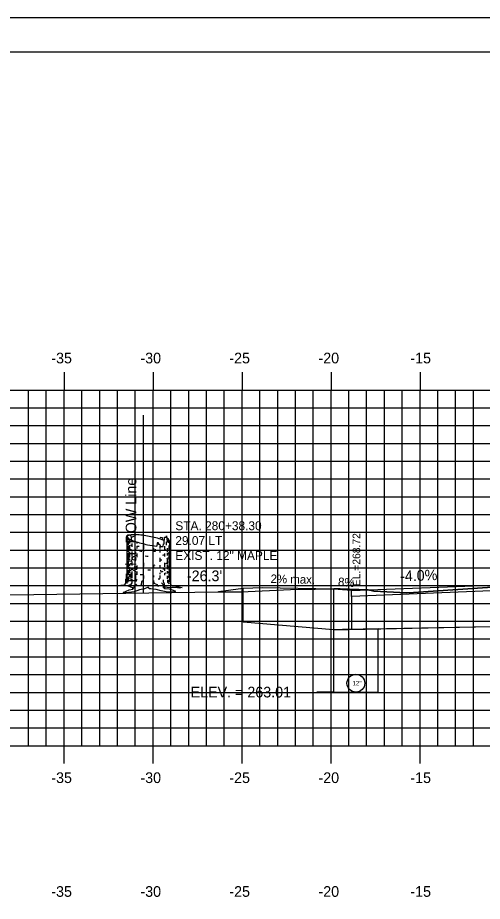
# Model space of a CAD drawing. Extents: x 855121 to 855291, y 366268 to 366378.
# Drawn here: x 855166.83 to 855192.94, y 366328.48 to 366378.18 of the extents above; entities that cross this region are included whole.
import ezdxf

# ---------------------------------------------------------------- set-up
doc = ezdxf.new("R2010")
doc.units = 0
for name, color, linetype in [('ANNOTATION', 7, 'Continuous'), ('BORDER', 7, 'Continuous'), ('D_Roadway_Drive_Gravel_LT', 7, 'Continuous'), ('D_Roadway_Drive_SubGrade', 7, 'Continuous'), ('D_Roadway_Edge_Shoulder', 7, 'Continuous'), ('D_Roadway_SubGrade', 7, 'Continuous'), ('D_Text_Monospaced', 7, 'Continuous'), ('D_Text_Standard', 7, 'Continuous'), ('E_ROW_Line', 7, 'Continuous'), ('H_V ANNOTATION', 7, 'Continuous'), ('JUNK COM EXC', 7, 'Continuous'), ('junk strct exc', 7, 'Continuous'), ('MAJOR', 7, 'Continuous'), ('MINOR', 7, 'Continuous'), ('PDRAIN', 7, 'Continuous'), ('PLOT BOUNDARY', 7, 'Continuous'), ('S_Roadway_Centerline', 7, 'Continuous'), ('S_Trees_Decid_Pay', 7, 'Continuous')]:
    doc.layers.add(name, color=color, linetype=linetype)

msp = doc.modelspace()

# ---------------------------------------------------------------- linework, layer by layer
at = {"layer": 'BORDER'}
msp.add_line((855289.442, 366376.236), (855129.442, 366376.236), dxfattribs=at)
at = {"layer": 'D_Roadway_Drive_Gravel_LT'}
for p, q in [((855184.587, 366346.037), (855180.587, 366346.117)), ((855184.587, 366346.037), (855180.587, 366346.117)), ((855185.587, 366345.957), (855184.587, 366346.037)), ((855185.587, 366345.957), (855184.587, 366346.037)), ((855185.587, 366345.623), (855185.587, 366345.957))]:
    msp.add_line(p, q, dxfattribs=at)
msp.add_lwpolyline([(855180.587, 366346.117), (855179.498, 366346.073), (855178.108, 366345.883)], dxfattribs=at)
at = {"layer": 'D_Roadway_Drive_SubGrade'}
for p, q in [((855179.498, 366344.185), (855179.498, 366346.073)), ((855184.587, 366343.75), (855179.498, 366344.185)), ((855185.587, 366343.78), (855184.587, 366343.75))]:
    msp.add_line(p, q, dxfattribs=at)
at = {"layer": 'D_Roadway_Edge_Shoulder'}
msp.add_lwpolyline([(855185.587, 366345.957), (855193.442, 366346.271), (855204.442, 366346.491), (855215.442, 366346.271), (855219.442, 366346.11)], dxfattribs=at)
at = {"layer": 'D_Roadway_SubGrade'}
msp.add_lwpolyline([(855193.442, 366345.938), (855185.587, 366345.623), (855185.587, 366343.78), (855193.442, 366343.938)], close=True, dxfattribs=at)
at = {"layer": 'D_Text_Standard'}
msp.add_lwpolyline([(855184.587, 366340.249), (855184.33, 366340.249), (855183.65, 366340.249)], dxfattribs=at)
at = {"layer": 'E_ROW_Line'}
msp.add_line((855173.902, 366345.821), (855173.902, 366355.821), dxfattribs=at)
at = {"layer": 'JUNK COM EXC'}
msp.add_lwpolyline([(855194.05, 366346.181), (855189.07, 366345.851), (855188.684, 366345.832), (855186.852, 366345.93), (855186.531, 366346.008), (855184.948, 366346.054), (855184.589, 366346.05), (855184.587, 366346.037), (855184.587, 366343.75), (855193.442, 366343.938)], dxfattribs=at)
at = {"layer": 'junk strct exc'}
msp.add_lwpolyline([(855184.587, 366343.75), (855184.587, 366340.249), (855187.087, 366340.249), (855187.087, 366343.81)], close=True, dxfattribs=at)
at = {"layer": 'MAJOR'}
for p, q in [((855169.442, 366358.238), (855169.442, 366357.236)), ((855174.442, 366358.238), (855174.442, 366357.236)), ((855179.442, 366358.238), (855179.442, 366357.236)), ((855184.442, 366358.238), (855184.442, 366357.236)), ((855189.442, 366358.238), (855189.442, 366357.236)), ((855134.442, 366357.236), (855274.442, 366357.236)), ((855134.442, 366357.236), (855274.442, 366357.236)), ((855169.442, 366337.236), (855169.442, 366357.236)), ((855174.442, 366337.236), (855174.442, 366357.236)), ((855179.442, 366337.236), (855179.442, 366357.236)), ((855184.442, 366337.236), (855184.442, 366357.236)), ((855189.442, 366337.236), (855189.442, 366357.236)), ((855134.442, 366352.236), (855274.442, 366352.236)), ((855134.442, 366347.236), (855274.442, 366347.236)), ((855134.442, 366342.236), (855274.442, 366342.236)), ((855134.442, 366337.236), (855274.442, 366337.236)), ((855134.442, 366337.236), (855274.442, 366337.236)), ((855169.442, 366336.234), (855169.442, 366337.236)), ((855174.442, 366336.234), (855174.442, 366337.236)), ((855179.442, 366336.234), (855179.442, 366337.236)), ((855184.442, 366336.234), (855184.442, 366337.236)), ((855189.442, 366336.234), (855189.442, 366337.236))]:
    msp.add_line(p, q, dxfattribs=at)
at = {"layer": 'MINOR'}
for p, q in [((855167.442, 366337.236), (855167.442, 366357.236)), ((855168.442, 366337.236), (855168.442, 366357.236)), ((855170.442, 366337.236), (855170.442, 366357.236)), ((855171.442, 366337.236), (855171.442, 366357.236)), ((855172.442, 366337.236), (855172.442, 366357.236)), ((855173.442, 366337.236), (855173.442, 366357.236)), ((855175.442, 366337.236), (855175.442, 366357.236)), ((855176.442, 366337.236), (855176.442, 366357.236)), ((855177.442, 366337.236), (855177.442, 366357.236)), ((855178.442, 366337.236), (855178.442, 366357.236)), ((855180.442, 366337.236), (855180.442, 366357.236)), ((855181.442, 366337.236), (855181.442, 366357.236)), ((855182.442, 366337.236), (855182.442, 366357.236)), ((855183.442, 366337.236), (855183.442, 366357.236)), ((855185.442, 366337.236), (855185.442, 366357.236)), ((855186.442, 366337.236), (855186.442, 366357.236)), ((855187.442, 366337.236), (855187.442, 366357.236)), ((855188.442, 366337.236), (855188.442, 366357.236)), ((855190.442, 366337.236), (855190.442, 366357.236)), ((855191.442, 366337.236), (855191.442, 366357.236)), ((855192.442, 366337.236), (855192.442, 366357.236)), ((855134.442, 366356.236), (855274.442, 366356.236)), ((855134.442, 366355.236), (855274.442, 366355.236)), ((855134.442, 366354.236), (855274.442, 366354.236)), ((855134.442, 366353.236), (855274.442, 366353.236)), ((855134.442, 366351.236), (855274.442, 366351.236)), ((855134.442, 366350.236), (855274.442, 366350.236)), ((855134.442, 366349.236), (855274.442, 366349.236)), ((855134.442, 366348.236), (855274.442, 366348.236)), ((855134.442, 366346.236), (855274.442, 366346.236)), ((855134.442, 366345.236), (855274.442, 366345.236)), ((855134.442, 366344.236), (855274.442, 366344.236)), ((855134.442, 366343.236), (855274.442, 366343.236)), ((855134.442, 366341.236), (855274.442, 366341.236)), ((855134.442, 366340.236), (855274.442, 366340.236)), ((855134.442, 366339.236), (855274.442, 366339.236)), ((855134.442, 366338.236), (855274.442, 366338.236))]:
    msp.add_line(p, q, dxfattribs=at)
at = {"layer": 'PDRAIN'}
msp.add_lwpolyline([(855184.587, 366343.75), (855184.587, 366340.249), (855187.087, 366340.249), (855187.087, 366343.75)], dxfattribs=at)
msp.add_circle((855185.837, 366340.749), 0.5, dxfattribs=at)
at = {"layer": 'PLOT BOUNDARY'}
msp.add_lwpolyline([(855121.349, 366268.177), (855291.349, 366268.177), (855291.349, 366378.177), (855121.349, 366378.177)], close=True, dxfattribs=at)
at = {"layer": 'S_Roadway_Centerline'}
msp.add_lwpolyline([(855144.138, 366345.236), (855154.981, 366345.612), (855167.747, 366345.731), (855178.089, 366345.883), (855179.388, 366345.897), (855182.154, 366346.026), (855184.948, 366346.054), (855186.531, 366346.008), (855186.852, 366345.93), (855188.684, 366345.832), (855189.07, 366345.851), (855194.05, 366346.181), (855199.995, 366346.43), (855204.747, 366346.643), (855214.965, 366346.488), (855215.768, 366346.474), (855220.431, 366346.316), (855220.775, 366346.323), (855220.997, 366346.289), (855221.747, 366346.285), (855225.306, 366346.406), (855236.796, 366346.885)], dxfattribs=at)
at = {"layer": 'S_Trees_Decid_Pay'}
for p, q in [((855173.043, 366348.9), (855173.043, 366348.779)), ((855173.043, 366348.727), (855173.043, 366348.513)), ((855173.123, 366348.855), (855173.123, 366348.602)), ((855173.123, 366348.505), (855173.123, 366348.242)), ((855173.256, 366348.602), (855173.256, 366348.41)), ((855173.528, 366348.688), (855173.528, 366348.602)), ((855173.911, 366348.587), (855173.911, 366348.307)), ((855175.168, 366348.696), (855175.168, 366348.522)), ((855173.043, 366348.468), (855173.043, 366348.13)), ((855173.043, 366348.013), (855173.043, 366347.652)), ((855173.123, 366348.145), (855173.123, 366347.836)), ((855173.256, 366348.159), (855173.256, 366347.881)), ((855173.528, 366348.461), (855173.528, 366348.322)), ((855173.528, 366348.036), (855173.528, 366347.844)), ((855173.911, 366348.242), (855173.911, 366348.139)), ((855174.457, 366348.351), (855174.457, 366348.171)), ((855174.584, 366348.178), (855174.579, 366348.285)), ((855174.822, 366348.45), (855174.822, 366348.33)), ((855174.822, 366348.278), (855174.822, 366348.093)), ((855175.083, 366348.448), (855175.083, 366348.243)), ((855175.083, 366348.036), (855175.083, 366347.881)), ((855175.232, 366348.351), (855175.232, 366348.139)), ((855175.232, 366348.073), (855175.232, 366347.925)), ((855175.318, 366348.496), (855175.318, 366348.242)), ((855175.318, 366348.145), (855175.318, 366347.675)), ((855173.043, 366347.616), (855173.043, 366347.167)), ((855173.123, 366347.748), (855173.123, 366347.681)), ((855173.256, 366347.836), (855173.256, 366347.727)), ((855173.256, 366347.593), (855173.256, 366347.364)), ((855173.911, 366347.527), (855173.911, 366347.307)), ((855174.822, 366347.807), (855174.822, 366347.579)), ((855175.083, 366347.519), (855175.083, 366347.299)), ((855175.232, 366347.748), (855175.232, 366347.447)), ((855175.318, 366347.624), (855175.318, 366347.49)), ((855173.043, 366347.101), (855173.043, 366346.819)), ((855173.123, 366347.447), (855173.123, 366347.35)), ((855173.123, 366347.299), (855173.123, 366346.938)), ((855173.256, 366347.035), (855173.256, 366346.652)), ((855173.528, 366347.364), (855173.528, 366347.156)), ((855173.528, 366347.035), (855173.528, 366346.835)), ((855174.457, 366347.393), (855174.457, 366347.196)), ((855174.822, 366347.381), (855174.822, 366347.196)), ((855175.083, 366347.199), (855175.083, 366347.078)), ((855175.232, 366347.41), (855175.232, 366347.167)), ((855175.232, 366347.056), (855175.232, 366346.916)), ((855175.318, 366347.433), (855175.318, 366347.107)), ((855175.318, 366347.078), (855175.318, 366346.658)), ((855173.123, 366346.887), (855173.123, 366346.72)), ((855173.533, 366346.578), (855173.453, 366346.446)), ((855173.911, 366346.807), (855173.911, 366346.633)), ((855174.457, 366346.813), (855174.457, 366346.709)), ((855174.822, 366346.961), (855174.822, 366346.884)), ((855174.822, 366346.807), (855174.822, 366346.633)), ((855175.083, 366346.927), (855175.083, 366346.829)), ((855175.232, 366346.784), (855175.232, 366346.627)), ((855175.314, 366346.555), (855175.329, 366346.438))]:
    msp.add_line(p, q, dxfattribs=at)
for points in [[(855175.012, 366348.443), (855175.02, 366348.587), (855175.065, 366348.58), (855175.079, 366348.954), (855175.174, 366348.962), (855175.188, 366349.042), (855175.226, 366348.705), (855175.271, 366348.799), (855175.291, 366348.645), (855175.368, 366348.771), (855175.362, 366348.581)], [(855175.368, 366348.771), (855175.368, 366346.633), (855175.388, 366346.492), (855175.394, 366346.366), (855175.438, 366346.279), (855175.53, 366346.23), (855175.666, 366346.23), (855175.909, 366346.174), (855176.076, 366346.125), (855175.934, 366346.094), (855175.697, 366346.131), (855175.487, 366346.119), (855175.226, 366346.125), (855175.102, 366346.143), (855175.071, 366346.101), (855175.009, 366346.143), (855175.108, 366346.076), (855175.343, 366346.051), (855175.573, 366345.989), (855175.703, 366345.919), (855175.604, 366345.876), (855175.182, 366345.895), (855174.904, 366345.938), (855174.606, 366346.014), (855174.32, 366346.051), (855174.215, 366346.051), (855174.196, 366346.131), (855174.128, 366346.137), (855173.961, 366346.051), (855173.675, 366345.995), (855173.377, 366345.888), (855172.917, 366345.839), (855172.763, 366345.851), (855173.105, 366346.001), (855173.308, 366346.032), (855173.297, 366346.106), (855173.037, 366346.206), (855172.862, 366346.236), (855172.621, 366346.248), (855172.819, 366346.286), (855172.881, 366346.322), (855172.905, 366346.409), (855172.917, 366346.578), (855172.963, 366346.664), (855172.991, 366346.905), (855172.991, 366348.991)], [(855174.85, 366348.448), (855174.814, 366348.551), (855174.748, 366348.557), (855174.748, 366348.639), (855174.674, 366348.645), (855174.649, 366348.465)], [(855174.989, 366348.809), (855174.968, 366348.917), (855174.837, 366348.948), (855174.829, 366348.86)], [(855175.368, 366348.771), (855175.322, 366348.793), (855175.3, 366348.859), (855175.248, 366348.882), (855175.215, 366348.807)], [(855173.415, 366347.17), (855173.416, 366347.247), (855173.424, 366347.313)], [(855174.96, 366347.078), (855174.968, 366347.004), (855174.894, 366346.998), (855174.88, 366347.115)], [(855173.041, 366346.747), (855172.981, 366346.586), (855172.967, 366346.461), (855172.975, 366346.364)], [(855173.098, 366346.666), (855173.027, 366346.563), (855173.027, 366346.438)], [(855173.239, 366346.592), (855173.239, 366346.387), (855173.181, 366346.277), (855173.084, 366346.261)], [(855173.894, 366346.518), (855173.791, 366346.467), (855173.776, 366346.261), (855173.673, 366346.232)], [(855174.459, 366346.526), (855174.476, 366346.372), (855174.674, 366346.292), (855174.719, 366346.188)], [(855175.102, 366346.143), (855175.083, 366346.322), (855175.022, 366346.459), (855175.028, 366346.559)], [(855175.248, 366346.563), (855175.255, 366346.438), (855175.337, 366346.343)], [(855173.308, 366346.032), (855173.395, 366346.174), (855173.527, 366346.316)], [(855174.911, 366346.391), (855174.985, 366346.322), (855175.003, 366346.224), (855175.009, 366346.143)]]:
    msp.add_lwpolyline(points, dxfattribs=at)
for centre, radius, start, end in [((855173.037, 366348.991), 0.0467, 157.54, 169.2221), ((855173.037, 366348.991), 0.0467, 169.2221, 180.9043), ((855173.044, 366348.988), 0.0544, 146.7221, 157.54), ((855173.053, 366348.983), 0.0645, 134.0453, 146.7221), ((855173.083, 366348.952), 0.107, 124.2221, 134.0453), ((855173.115, 366348.905), 0.164, 110.0157, 124.2221), ((855173.223, 366348.609), 0.48, 101.7221, 110.0157), ((855173.389, 366347.806), 1.299, 86.3056, 101.7221), ((855173.078, 366342.99), 6.126, 79.2221, 86.3056), ((855173.078, 366342.99), 6.126, 72.1387, 79.2221), ((855173.045, 366348.991), 0.0544, 180.9043, 191.7221), ((855173.045, 366348.665), 0.0554, 191.6815, 202.5), ((855173.055, 366348.993), 0.0645, 191.7221, 204.3989), ((855173.054, 366348.668), 0.0657, 202.5, 215.1737), ((855173.094, 366349.011), 0.107, 204.3989, 214.2221), ((855173.09, 366348.693), 0.109, 215.1737, 225), ((855173.141, 366349.043), 0.164, 214.2221, 228.4286), ((855173.13, 366348.734), 0.166, 225, 238.33), ((855173.35, 366349.279), 0.48, 228.4286, 236.7221), ((855173.8, 366349.964), 1.299, 236.7221, 252.1387), ((855173.602, 366349.753), 1.292, 250.9084, 254.4349), ((855175.28, 366354.558), 6.126, 252.1387, 259.2221), ((855175.28, 366354.558), 6.126, 259.2221, 264.0853), ((855174.558, 366347.583), 1.299, 66.6931, 72.1387), ((855173.046, 366348.404), 0.0554, 191.6815, 202.5), ((855173.055, 366348.408), 0.0657, 202.5, 215.1737), ((855173.091, 366348.433), 0.109, 215.1737, 225), ((855173.131, 366348.473), 0.166, 225, 239.1924), ((855173.131, 366348.21), 0.166, 238.3999, 239.1924), ((855173.294, 366348.746), 0.484, 239.1924, 242.5838), ((855173.294, 366348.483), 0.484, 239.1924, 247.5), ((855173.603, 366349.492), 1.292, 247.5, 251.9171), ((855173.603, 366349.229), 1.292, 247.5, 248.1929), ((855174.178, 366354.341), 5.916, 263.6913, 265.0485), ((855174.179, 366354.08), 5.916, 265.1076, 266.4618), ((855174.179, 366354.08), 5.916, 272.6957, 273.9224), ((855175.28, 366354.558), 6.126, 265.9754, 266.3056), ((855174.969, 366349.742), 1.299, 266.3056, 271.8711), ((855174.755, 366349.492), 1.292, 284.7144, 289.3881), ((855174.755, 366349.229), 1.292, 291.6463, 292.5), ((855175.064, 366348.483), 0.484, 292.5, 300.8076), ((855175.227, 366348.473), 0.166, 300.8076, 315), ((855175.227, 366348.21), 0.166, 300.8076, 302.9622), ((855175.268, 366348.433), 0.109, 315, 324.8263), ((855175.303, 366348.408), 0.0657, 324.8263, 337.5), ((855175.313, 366348.404), 0.0554, 337.5, 348.3185), ((855175.32, 366348.402), 0.0476, 348.3185, 0), ((855173.046, 366347.883), 0.0554, 191.6815, 202.5), ((855173.046, 366347.625), 0.0554, 191.6815, 202.5), ((855173.055, 366347.887), 0.0657, 202.5, 215.1737), ((855173.055, 366347.629), 0.0657, 202.5, 215.1737), ((855173.091, 366347.912), 0.109, 215.1737, 225), ((855173.091, 366347.654), 0.109, 215.1737, 225), ((855173.131, 366347.952), 0.166, 225, 239.1924), ((855173.131, 366347.695), 0.166, 225, 237.9306), ((855173.294, 366348.225), 0.484, 239.1924, 245.3628), ((855173.603, 366348.972), 1.292, 254.3895, 260.7435), ((855173.603, 366349.229), 1.292, 261.6338, 262.8454), ((855174.179, 366353.817), 5.916, 262.8454, 263.6816), ((855174.179, 366353.817), 5.916, 268.2292, 269.8838), ((855174.179, 366353.559), 5.916, 276.2405, 277.1546), ((855174.755, 366348.972), 1.292, 277.1546, 278.1274), ((855174.755, 366349.229), 1.292, 280.7368, 284.7144), ((855174.755, 366348.714), 1.292, 288.201, 292.5), ((855174.755, 366348.972), 1.292, 291.5158, 292.5), ((855175.064, 366348.225), 0.484, 294.2275, 300.8076), ((855175.227, 366347.952), 0.166, 300.8076, 315), ((855175.227, 366347.695), 0.166, 300.8076, 315), ((855175.268, 366347.912), 0.109, 315, 324.8263), ((855175.268, 366347.654), 0.109, 315, 324.8263), ((855175.303, 366347.887), 0.0657, 324.8263, 337.5), ((855175.303, 366347.629), 0.0657, 324.8263, 337.5), ((855175.313, 366347.883), 0.0554, 337.5, 348.3185), ((855175.313, 366347.625), 0.0554, 337.5, 348.3185), ((855175.32, 366347.881), 0.0476, 348.3185, 0), ((855175.32, 366347.624), 0.0476, 348.3185, 0), ((855173.046, 366347.36), 0.0554, 191.6815, 202.5), ((855173.046, 366347.088), 0.0554, 191.6815, 202.5), ((855173.055, 366347.092), 0.0657, 202.5, 215.1737), ((855173.091, 366347.117), 0.109, 215.1737, 225), ((855173.131, 366347.158), 0.166, 225, 237.9306), ((855173.131, 366347.429), 0.166, 237.9306, 239.1924), ((855173.294, 366347.702), 0.484, 239.1924, 247.5), ((855173.603, 366348.714), 1.292, 249.8999, 254.3895), ((855173.603, 366348.449), 1.292, 261.6205, 262.8454), ((855174.179, 366353.037), 5.916, 262.8454, 263.6816), ((855174.179, 366353.037), 5.916, 269.7243, 270), ((855174.179, 366353.037), 5.916, 270, 271.0793), ((855174.179, 366353.302), 5.916, 272.6957, 273.7279), ((855174.755, 366348.449), 1.292, 280.7537, 284.7144), ((855174.755, 366348.449), 1.292, 291.6463, 292.5), ((855175.064, 366347.702), 0.484, 292.5, 300.8076), ((855175.227, 366347.429), 0.166, 300.8076, 315), ((855175.268, 366347.389), 0.109, 315, 324.8263), ((855175.303, 366347.364), 0.0657, 324.8263, 337.5), ((855175.313, 366347.36), 0.0554, 337.5, 348.3185), ((855175.32, 366347.358), 0.0476, 348.3185, 0), ((855173.294, 366347.173), 0.484, 243.4501, 247.5), ((855173.594, 366347.923), 1.292, 247.9396, 248.6304), ((855173.603, 366348.177), 1.292, 250.8466, 254.3895), ((855173.603, 366348.177), 1.292, 261.6338, 262.8454), ((855174.179, 366352.765), 5.916, 262.8454, 263.6816), ((855174.179, 366352.765), 5.916, 265.539, 266.7363), ((855174.179, 366352.507), 5.916, 275.2344, 276.2169), ((855174.755, 366348.177), 1.292, 284.7144, 288.6336), ((855174.755, 366347.919), 1.292, 291.6463, 292.5), ((855175.064, 366347.431), 0.484, 292.5, 297.266), ((855175.064, 366347.173), 0.484, 292.5, 300.8076), ((855175.227, 366346.9), 0.166, 300.8076, 315), ((855175.268, 366346.86), 0.109, 315, 324.8263), ((855175.303, 366346.835), 0.0657, 324.8263, 337.5), ((855175.313, 366346.831), 0.0554, 337.5, 348.3185), ((855175.32, 366346.829), 0.0476, 348.3185, 0)]:
    msp.add_arc(centre, radius, start, end, dxfattribs=at)

# ---------------------------------------------------------------- texts
at = {"layer": 'ANNOTATION'}
msp.add_text('-4.0%', height=0.6, rotation=2.2906, dxfattribs=at).set_placement((855188.331, 366346.467))
at = {"layer": 'D_Roadway_Drive_Gravel_LT'}
for s, rotation, p in [('2% max.', 358.8078, (855181.041, 366346.387)), ('8%', 355.4261, (855184.818, 366346.224))]:
    msp.add_text(s, height=0.48, rotation=rotation, dxfattribs=at).set_placement(p)
at = {"layer": 'D_Text_Monospaced'}
for s, height, p in [('STA. 280+38.30', 0.49998, (855175.691, 366349.355)), ('29.07 LT.', 0.5, (855175.691, 366348.521)), ('EXIST. 12" MAPLE', 0.49998, (855175.691, 366347.681))]:
    msp.add_text(s, height=height, dxfattribs=at).set_placement(p)
at = {"layer": 'D_Text_Standard'}
msp.add_text(' EL.=268.72', height=0.4335, rotation=90, dxfattribs=at).set_placement((855186.085, 366346.045))
for s, p in [("-26.3'", (855176.341, 366346.488)), ('ELEV. = 263.01', (855176.55, 366339.949))]:
    msp.add_text(s, height=0.6, dxfattribs=at).set_placement(p)
at = {"layer": 'E_ROW_Line'}
msp.add_text('Exist. ROW Line', height=0.6, rotation=90, dxfattribs=at).set_placement((855173.502, 366346.421))
at = {"layer": 'H_V ANNOTATION'}
for s, p in [('-35', (855168.722, 366358.736)), ('-30', (855173.73, 366358.736)), ('-25', (855178.727, 366358.736)), ('-20', (855183.735, 366358.736)), ('-15', (855188.899, 366358.736)), ('-35', (855168.722, 366335.136)), ('-30', (855173.73, 366335.136)), ('-25', (855178.727, 366335.136)), ('-20', (855183.735, 366335.136)), ('-15', (855188.899, 366335.136)), ('-35', (855168.722, 366328.736)), ('-30', (855173.73, 366328.736)), ('-25', (855178.727, 366328.736)), ('-20', (855183.735, 366328.736)), ('-15', (855188.899, 366328.736))]:
    msp.add_text(s, height=0.6, dxfattribs=at).set_placement(p)
at = {"layer": 'PDRAIN'}
msp.add_text('12"', height=0.25, dxfattribs=at).set_placement((855185.646, 366340.624))

doc.saveas('drawing.dxf')
